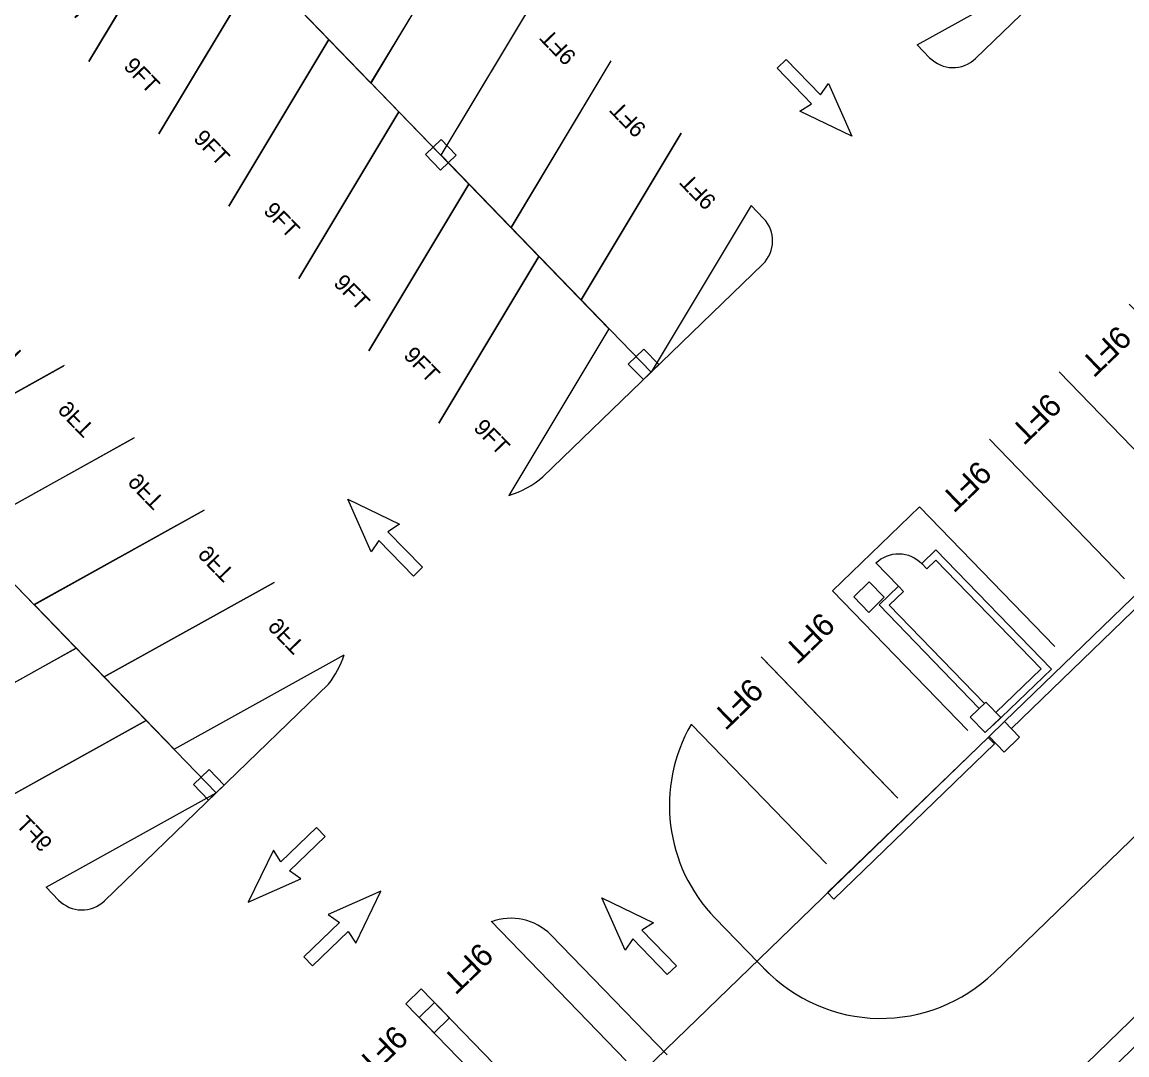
# Model space of a CAD drawing. Extents: x 468143 to 491361, y 1438528 to 1468730.
# Drawn here: x 490314.2 to 490416.5, y 1467316.1 to 1467411.7 of the extents above; entities that cross this region are included whole.
import ezdxf

# ---------------------------------------------------------------- set-up
doc = ezdxf.new("R2010")
doc.units = 0
doc.layers.add('Default', color=7, linetype='Continuous')
doc.layers.add('Xreference_dp', color=7, linetype='Continuous')

# ---------------------------------------------------------------- blocks, each defined once
blk = doc.blocks.new('STALL 9FT-75D')
at = {"layer": 'Default'}
for p, q in [((0, 0), (111.8, 0)), ((111.8, 0), (167.7, -208.6))]:
    blk.add_line(p, q, dxfattribs=at)
blk.add_lwpolyline([(55.9, -208.6), (0, 0)], dxfattribs=at)
blk.add_text('9FT', height=18, dxfattribs=at).set_placement((86.4, -185.9))
blk = doc.blocks.new('STALL 9FT')
at = {"layer": 'Default'}
for points in [[(0, 0), (0, 216)], [(108, 216), (108, 0)]]:
    blk.add_lwpolyline(points, dxfattribs=at)
blk.add_text('9FT', height=25, dxfattribs=at).set_placement((24.7, 7.1))
blk = doc.blocks.new('arrow-thru')
at = {"layer": 'Default'}
blk.add_lwpolyline([(14.99997, 0), (28.999942, 0), (28.999942, 54.99989), (43.999912, 51.999896), (21.999956, 111.999776), (0, 51.999896), (14.99997, 54.99989)], close=True, dxfattribs=at)
blk = doc.blocks.new('door')
at = {"layer": 'Default'}
blk.add_line((0, 0), (0, 36), dxfattribs=at)
blk.add_arc((0, 0), 36, 90, 180, dxfattribs=at)
blk = doc.blocks.new('Col 24x24')
at = {"layer": 'Default'}
blk.add_lwpolyline([(-11.999976, -11.999976), (-11.999976, 11.999976), (11.999976, 11.999976), (11.999976, -11.999976), (-11.999976, -11.999976)], dxfattribs=at)
blk.add_lwpolyline([(-11.999976, -11.999976), (11.999976, -11.999976), (11.999976, 11.999976), (-11.999976, 11.999976)], close=True, dxfattribs=at)

msp = doc.modelspace()

# ---------------------------------------------------------------- linework, layer by layer
at = {"layer": 'Xreference_dp'}
for p, q in [((490412.78, 1467418.34), (490402.44, 1467408.34)), ((490412.78, 1467418.34), (490402.44, 1467408.34)), ((490397.05, 1467409.6), (490398.2, 1467408.41)), ((490397.05, 1467409.6), (490398.2, 1467408.41)), ((490381.67, 1467394.73), (490382.82, 1467393.54)), ((490381.67, 1467394.73), (490382.82, 1467393.54)), ((490405.14, 1467346.95), (490451.41, 1467391.73)), ((490405.14, 1467346.95), (490451.41, 1467391.73)), ((490372.42, 1467379.29), (490382.75, 1467389.3)), ((490372.42, 1467379.29), (490382.75, 1467389.3)), ((490455.86, 1467373.77), (490404.13, 1467323.68)), ((490455.86, 1467373.77), (490404.13, 1467323.68)), ((490389.22, 1467359.04), (490397.26, 1467366.82)), ((490389.22, 1467359.04), (490397.26, 1467366.82)), ((490397.48, 1467361.57), (490397.94, 1467361.09)), ((490397.48, 1467361.57), (490397.94, 1467361.09)), ((490395.32, 1467359.48), (490395.79, 1467359)), ((490395.32, 1467359.48), (490395.79, 1467359)), ((490459.82, 1467358.12), (490384.21, 1467284.96)), ((490459.82, 1467358.12), (490384.21, 1467284.96)), ((490363.46, 1467306.61), (490403.7, 1467345.55)), ((490363.46, 1467306.61), (490403.7, 1467345.55)), ((490332.18, 1467340.35), (490321.84, 1467330.34)), ((490332.18, 1467340.35), (490321.84, 1467330.34)), ((490316.44, 1467331.61), (490317.59, 1467330.41)), ((490316.44, 1467331.61), (490317.59, 1467330.41)), ((490373.92, 1467316.08), (490363.14, 1467327.21)), ((490373.92, 1467316.08), (490363.14, 1467327.21)), ((490423.9, 1467326.12), (490412.71, 1467315.29)), ((490423.9, 1467326.12), (490412.71, 1467315.29)), ((490349.72, 1467320.81), (490351.14, 1467322.19)), ((490349.72, 1467320.81), (490351.14, 1467322.19))]:
    msp.add_line(p, q, dxfattribs=at)
for points in [[(490451.66, 1467390.7), (490405.77, 1467346.29)], [(490451.66, 1467390.7), (490405.77, 1467346.29)], [(490362.4, 1467369.6), (490372.42, 1467379.29)], [(490362.4, 1467369.6), (490372.42, 1467379.29)], [(490397.48, 1467361.57), (490398.79, 1467362.84), (490409.47, 1467351.81), (490404.08, 1467346.6)], [(490397.48, 1467361.57), (490398.79, 1467362.84), (490409.47, 1467351.81), (490404.08, 1467346.6)], [(490404.34, 1467347.77), (490408.53, 1467351.83), (490398.78, 1467361.9), (490397.94, 1467361.09)], [(490404.34, 1467347.77), (490408.53, 1467351.83), (490398.78, 1467361.9), (490397.94, 1467361.09)], [(490402.8, 1467348.16), (490393.53, 1467357.74), (490395.32, 1467359.48)], [(490402.8, 1467348.16), (490393.53, 1467357.74), (490395.32, 1467359.48)], [(490395.79, 1467359), (490394.47, 1467357.73), (490403.28, 1467348.63)], [(490395.79, 1467359), (490394.47, 1467357.73), (490403.28, 1467348.63)], [(490342.57, 1467350.41), (490332.24, 1467340.41)], [(490342.57, 1467350.41), (490332.24, 1467340.41)], [(490388.76, 1467331.1), (490403.62, 1467345.48), (490404.2, 1467344.88), (490389.34, 1467330.5), (490388.76, 1467331.1)], [(490388.76, 1467331.1), (490403.62, 1467345.48), (490404.2, 1467344.88), (490389.34, 1467330.5), (490388.76, 1467331.1)], [(490383.33, 1467323.61), (490378.35, 1467328.75)], [(490383.33, 1467323.61), (490378.35, 1467328.75)]]:
    msp.add_lwpolyline(points, dxfattribs=at)
for centre, radius, start, end in [((488571.3, 1469355.06), 2903.53, 306.9274, 317.95297), ((488571.3, 1469355.06), 2904.28, 306.9274, 317.95297), ((488571.3, 1469355.06), 2905.78, 306.9274, 317.95297), ((490400.36, 1467410.5), 3, 224.0571, 314.0571), ((490400.36, 1467410.5), 3, 224.0571, 314.0571), ((488571.3, 1469355.06), 2911.78, 306.9274, 317.95297), ((488571.3, 1469355.06), 2923.78, 306.9274, 317.95297), ((490380.67, 1467391.45), 3, 314.0571, 44.0571), ((490380.67, 1467391.45), 3, 314.0571, 44.0571), ((488571.3, 1469355.06), 2935.78, 306.9274, 317.95297), ((488571.3, 1469355.06), 2947.78, 306.9274, 317.95297), ((488571.3, 1469355.06), 2947.78, 306.9274, 317.95297), ((488571.3, 1469355.06), 2949.28, 306.9274, 317.95297), ((488571.3, 1469355.06), 2949.78, 306.9274, 317.95297), ((490356.81, 1467376.07), 8.55, 286.6869, 310.8574), ((490356.81, 1467376.07), 8.55, 286.6869, 310.8574), ((490334.91, 1467356.22), 9.62, 322.8196, 341.1637), ((490334.91, 1467356.22), 9.62, 322.8196, 341.1637), ((490389.12, 1467339.18), 15, 149.9845, 224.0629), ((490389.12, 1467339.18), 15, 149.9845, 224.0629), ((490319.75, 1467332.5), 3, 224.0571, 314.0571), ((490319.75, 1467332.5), 3, 224.0571, 314.0571), ((490359.45, 1467323.5), 5.23, 45.1755, 110.2424), ((490359.45, 1467323.5), 5.23, 45.1755, 110.2424), ((490393.7, 1467334.46), 15, 224.0371, 314.0785), ((490393.7, 1467334.46), 15, 224.0371, 314.0785)]:
    msp.add_arc(centre, radius, start, end, dxfattribs=at)

# ---------------------------------------------------------------- block references
for name, p, xscale, yscale, rotation in [('STALL 9FT-75D', (490323.17, 1467430.19), 0.08333072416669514, 0.08333072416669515, -45.942932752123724), ('STALL 9FT-75D', (490323.17, 1467430.19), 0.08333072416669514, 0.08333072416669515, -45.942932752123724), ('STALL 9FT-75D', (490412.78, 1467418.34), 0.08333072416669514, -0.08333072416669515, 134.0570672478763), ('STALL 9FT-75D', (490412.78, 1467418.34), 0.08333072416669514, -0.08333072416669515, 134.0570672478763), ('STALL 9FT-75D', (490346.5, 1467406.07), 0.0833307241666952, 0.08333072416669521, 134.05706724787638), ('STALL 9FT-75D', (490346.5, 1467406.07), 0.0833307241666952, 0.08333072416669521, 134.05706724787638), ('STALL 9FT-75D', (490329.65, 1467423.49), 0.08333072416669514, 0.08333072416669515, -45.942932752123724), ('STALL 9FT-75D', (490329.65, 1467423.49), 0.08333072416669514, 0.08333072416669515, -45.942932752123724), ('STALL 9FT-75D', (490352.98, 1467399.38), 0.0833307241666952, 0.08333072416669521, 134.05706724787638), ('STALL 9FT-75D', (490352.98, 1467399.38), 0.0833307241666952, 0.08333072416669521, 134.05706724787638), ('STALL 9FT-75D', (490336.12, 1467416.8), 0.08333072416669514, 0.08333072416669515, -45.942932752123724), ('STALL 9FT-75D', (490336.12, 1467416.8), 0.08333072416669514, 0.08333072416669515, -45.942932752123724), ('STALL 9FT-75D', (490359.46, 1467392.68), 0.0833307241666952, 0.08333072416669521, 134.05706724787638), ('STALL 9FT-75D', (490359.46, 1467392.68), 0.0833307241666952, 0.08333072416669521, 134.05706724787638), ('STALL 9FT-75D', (490342.6, 1467410.1), 0.08333072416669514, 0.08333072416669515, -45.942932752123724), ('STALL 9FT-75D', (490342.6, 1467410.1), 0.08333072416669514, 0.08333072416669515, -45.942932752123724), ('arrow-thru', (490383.19, 1467406.58), 0.08333072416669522, -0.08333072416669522, 44.057067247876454), ('arrow-thru', (490383.19, 1467406.58), 0.08333072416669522, -0.08333072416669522, 44.057067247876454), ('STALL 9FT-75D', (490365.94, 1467385.99), 0.0833307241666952, 0.08333072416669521, 134.05706724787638), ('STALL 9FT-75D', (490365.94, 1467385.99), 0.0833307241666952, 0.08333072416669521, 134.05706724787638), ('STALL 9FT-75D', (490349.08, 1467403.41), 0.08333072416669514, 0.08333072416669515, -45.942932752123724), ('STALL 9FT-75D', (490349.08, 1467403.41), 0.08333072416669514, 0.08333072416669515, -45.942932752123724), ('Col 24x24', (490352.96, 1467399.42), 0.0833307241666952, 0.0833307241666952, 44.062944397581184), ('Col 24x24', (490352.96, 1467399.42), 0.0833307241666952, 0.0833307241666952, 44.062944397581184), ('STALL 9FT-75D', (490372.42, 1467379.29), 0.0833307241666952, 0.08333072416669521, 134.05706724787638), ('STALL 9FT-75D', (490372.42, 1467379.29), 0.0833307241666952, 0.08333072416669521, 134.05706724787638), ('STALL 9FT-75D', (490355.56, 1467396.71), 0.08333072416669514, 0.08333072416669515, -45.942932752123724), ('STALL 9FT-75D', (490355.56, 1467396.71), 0.08333072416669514, 0.08333072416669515, -45.942932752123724), ('STALL 9FT-75D', (490295.88, 1467377.85), 0.0833307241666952, -0.0833307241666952, -45.94293275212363), ('STALL 9FT-75D', (490295.88, 1467377.85), 0.0833307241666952, -0.0833307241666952, -45.94293275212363), ('STALL 9FT-75D', (490362.04, 1467390.01), 0.08333072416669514, 0.08333072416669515, -45.942932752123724), ('STALL 9FT-75D', (490362.04, 1467390.01), 0.08333072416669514, 0.08333072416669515, -45.942932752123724), ('STALL 9FT', (490416.67, 1467385.6), 0.08333072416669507, 0.08333072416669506, -135.94293275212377), ('STALL 9FT', (490416.67, 1467385.6), 0.08333072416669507, 0.08333072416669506, -135.94293275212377), ('STALL 9FT-75D', (490302.36, 1467371.16), 0.0833307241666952, -0.0833307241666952, -45.94293275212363), ('STALL 9FT-75D', (490302.36, 1467371.16), 0.0833307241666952, -0.0833307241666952, -45.94293275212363), ('Col 24x24', (490371.73, 1467380.02), 0.0833307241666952, 0.0833307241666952, 44.062944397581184), ('Col 24x24', (490371.73, 1467380.02), 0.0833307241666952, 0.0833307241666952, 44.062944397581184), ('STALL 9FT', (490410.2, 1467379.34), 0.08333072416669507, 0.08333072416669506, -135.94293275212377), ('STALL 9FT', (490410.2, 1467379.34), 0.08333072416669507, 0.08333072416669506, -135.94293275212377), ('STALL 9FT-75D', (490308.84, 1467364.46), 0.0833307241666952, -0.0833307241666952, -45.94293275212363), ('STALL 9FT-75D', (490308.84, 1467364.46), 0.0833307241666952, -0.0833307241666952, -45.94293275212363), ('STALL 9FT', (490403.73, 1467373.08), 0.08333072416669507, 0.08333072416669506, -135.94293275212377), ('STALL 9FT', (490403.73, 1467373.08), 0.08333072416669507, 0.08333072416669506, -135.94293275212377), ('STALL 9FT-75D', (490315.32, 1467357.77), 0.0833307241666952, -0.0833307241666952, -45.94293275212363), ('STALL 9FT-75D', (490315.32, 1467357.77), 0.0833307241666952, -0.0833307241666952, -45.94293275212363), ('arrow-thru', (490352.16, 1467362.1), 0.0833307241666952, -0.08333072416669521, -135.9429327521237), ('arrow-thru', (490352.16, 1467362.1), 0.0833307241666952, -0.08333072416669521, -135.9429327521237), ('STALL 9FT-75D', (490319.22, 1467353.74), 0.08333072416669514, -0.08333072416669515, 134.0570672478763), ('STALL 9FT-75D', (490319.22, 1467353.74), 0.08333072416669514, -0.08333072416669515, 134.0570672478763), ('STALL 9FT-75D', (490321.8, 1467351.07), 0.0833307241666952, -0.0833307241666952, -45.94293275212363), ('STALL 9FT-75D', (490321.8, 1467351.07), 0.0833307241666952, -0.0833307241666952, -45.94293275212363), ('door', (490395.32, 1467359.48), 0.0833307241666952, -0.0833307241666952, -135.93705560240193), ('door', (490395.32, 1467359.48), 0.0833307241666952, -0.0833307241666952, -135.93705560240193), ('Col 24x24', (490392.59, 1467358.47), 0.0833307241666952, 0.0833307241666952, 44.062944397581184), ('Col 24x24', (490392.59, 1467358.47), 0.0833307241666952, 0.0833307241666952, 44.062944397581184), ('STALL 9FT', (490389.22, 1467359.04), 0.08333072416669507, 0.08333072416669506, -135.94293275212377), ('STALL 9FT', (490389.22, 1467359.04), 0.08333072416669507, 0.08333072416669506, -135.94293275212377), ('STALL 9FT-75D', (490325.7, 1467347.04), 0.08333072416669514, -0.08333072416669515, 134.0570672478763), ('STALL 9FT-75D', (490325.7, 1467347.04), 0.08333072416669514, -0.08333072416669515, 134.0570672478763), ('STALL 9FT', (490382.6, 1467352.95), 0.08333072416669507, 0.08333072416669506, -135.94293275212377), ('STALL 9FT', (490382.6, 1467352.95), 0.08333072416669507, 0.08333072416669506, -135.94293275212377), ('STALL 9FT-75D', (490332.18, 1467340.35), 0.08333072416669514, -0.08333072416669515, 134.0570672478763), ('STALL 9FT-75D', (490332.18, 1467340.35), 0.08333072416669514, -0.08333072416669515, 134.0570672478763), ('Col 24x24', (490403.37, 1467347.33), 0.0833307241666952, 0.0833307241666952, 44.062944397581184), ('Col 24x24', (490403.37, 1467347.33), 0.0833307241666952, 0.0833307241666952, 44.062944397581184), ('Col 24x24', (490405.11, 1467345.53), 0.0833307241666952, 0.0833307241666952, 44.062944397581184), ('Col 24x24', (490405.11, 1467345.53), 0.0833307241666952, 0.0833307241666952, 44.062944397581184), ('Col 24x24', (490331.49, 1467341.08), 0.0833307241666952, 0.0833307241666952, 44.062944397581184), ('Col 24x24', (490331.49, 1467341.08), 0.0833307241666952, 0.0833307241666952, 44.062944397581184), ('arrow-thru', (490343.13, 1467335.4), 0.0833307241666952, 0.08333072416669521, 134.05706724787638), ('arrow-thru', (490343.13, 1467335.4), 0.0833307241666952, 0.08333072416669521, 134.05706724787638), ('arrow-thru', (490339.42, 1467326.06), 0.0833307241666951, 0.08333072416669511, -45.942932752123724), ('arrow-thru', (490339.42, 1467326.06), 0.0833307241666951, 0.08333072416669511, -45.942932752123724), ('arrow-thru', (490375.66, 1467325.2), 0.08333072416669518, -0.08333072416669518, -135.93706329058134), ('arrow-thru', (490375.66, 1467325.2), 0.08333072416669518, -0.08333072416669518, -135.93706329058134), ('STALL 9FT', (490357.61, 1467328.45), 0.08333072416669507, 0.08333072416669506, -135.94293275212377), ('STALL 9FT', (490357.61, 1467328.45), 0.08333072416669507, 0.08333072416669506, -135.94293275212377), ('Col 24x24', (490352.36, 1467319.52), 0.0833307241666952, 0.0833307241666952, 44.062944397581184), ('Col 24x24', (490352.36, 1467319.52), 0.0833307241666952, 0.0833307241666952, 44.062944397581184), ('STALL 9FT', (490349.72, 1467320.81), 0.08333072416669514, 0.08333072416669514, -135.9429327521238), ('STALL 9FT', (490349.72, 1467320.81), 0.08333072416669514, 0.08333072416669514, -135.9429327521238)]:
    msp.add_blockref(name, p, dxfattribs=dict(at, xscale=xscale, yscale=yscale, rotation=rotation))

doc.saveas('drawing.dxf')
